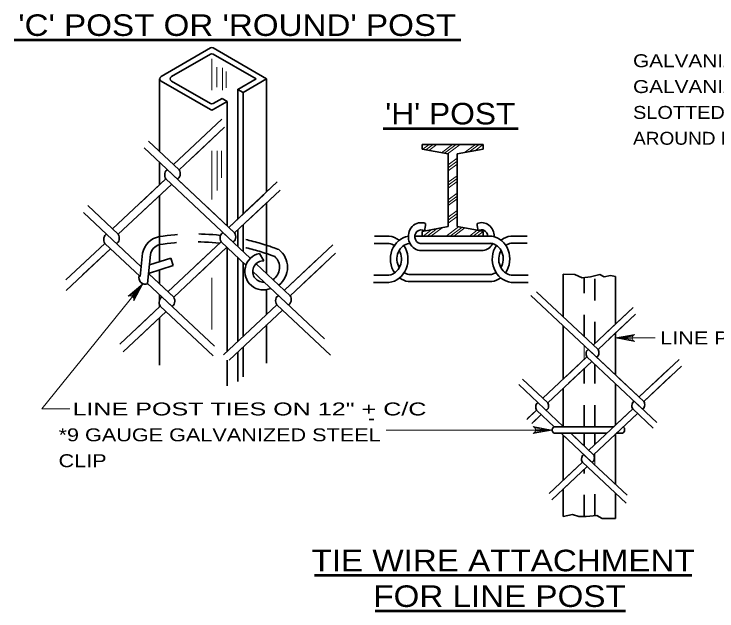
# Model space of a CAD drawing. Extents: x -29.89 to -22.78, y 99.65 to 109.34.
# Drawn here: x -29.886 to -26.626, y 106.552 to 109.322 of the extents above; entities that cross this region are included whole.
import ezdxf
from ezdxf.enums import TextEntityAlignment as Align

# ---------------------------------------------------------------- set-up
doc = ezdxf.new("R2010")
doc.units = 0
doc.header["$LTSCALE"] = 0.024
doc.linetypes.add('SHORT_DASHED', pattern=[2.7, 1.5, -1.2])
for name, color, linetype, lineweight in [('1', 7, 'Continuous', 35), ('10', 7, 'Continuous', 13), ('12', 7, 'Continuous', 53), ('6', 7, 'Continuous', 13)]:
    doc.layers.add(name, color=color, linetype=linetype, lineweight=lineweight)

msp = doc.modelspace()

# ---------------------------------------------------------------- linework, layer by layer
at = {"layer": '1'}
for p, q in [((-29.20419, 109.0319), (-28.9746, 109.16444)), ((-28.96237, 109.16444), (-28.71446, 109.02129)), ((-29.15529, 109.03187), (-28.9746, 109.13621)), ((-28.96237, 109.13621), (-28.76335, 109.02131)), ((-29.21104, 109.02129), (-29.21104, 108.68415)), ((-29.20419, 109.01071), (-28.9746, 108.87817)), ((-29.15529, 109.01071), (-28.9746, 108.9064)), ((-28.71446, 109.02129), (-28.82358, 108.95829)), ((-28.71446, 109.02129), (-28.71446, 108.84885)), ((-28.71446, 109.02129), (-28.71446, 108.49612)), ((-28.84802, 108.97242), (-28.82358, 108.95829)), ((-28.84802, 108.97242), (-28.84802, 108.37069)), ((-28.82358, 108.95829), (-28.82358, 108.83994)), ((-28.82358, 108.95829), (-28.82358, 108.39365)), ((-28.96237, 108.9064), (-28.92119, 108.93017)), ((-28.96237, 108.87817), (-28.89675, 108.91606)), ((-28.92119, 108.93017), (-28.89675, 108.91606)), ((-28.89675, 108.91606), (-28.89675, 108.82658)), ((-28.89675, 108.91606), (-28.89675, 108.33875)), ((-28.92231, 108.83435), (-29.14665, 108.62367)), ((-28.92231, 108.83435), (-29.07192, 108.69385)), ((-28.90896, 108.79671), (-29.11992, 108.59856)), ((-28.90894, 108.79671), (-29.05856, 108.65619)), ((-29.26156, 108.7316), (-29.11992, 108.59856)), ((-27.99302, 108.7171), (-27.71019, 108.7171)), ((-27.99302, 108.6949), (-27.99302, 108.7171)), ((-27.71019, 108.6949), (-27.71019, 108.7171)), ((-29.28173, 108.70033), (-28.86265, 108.30673)), ((-27.87181, 108.67267), (-27.99302, 108.6949)), ((-27.83142, 108.67267), (-27.71019, 108.6949)), ((-27.87181, 108.67267), (-27.87181, 108.33565)), ((-27.83142, 108.67267), (-27.83142, 108.33565)), ((-29.21104, 108.63394), (-29.21104, 108.52971)), ((-29.17338, 108.59856), (-28.86265, 108.30673)), ((-29.18227, 108.55673), (-29.42921, 108.32481)), ((-29.18227, 108.55673), (-29.29838, 108.44769)), ((-29.18227, 108.55673), (-28.87156, 108.2649)), ((-29.15554, 108.53162), (-29.40248, 108.29971)), ((-29.15554, 108.53162), (-29.28502, 108.41002)), ((-28.66506, 108.54252), (-28.88937, 108.33183)), ((-28.66506, 108.54252), (-28.81467, 108.402)), ((-28.65169, 108.50487), (-28.86265, 108.30673)), ((-28.65169, 108.50487), (-28.80129, 108.36435)), ((-29.21104, 108.4795), (-29.21104, 108.17287)), ((-28.88937, 108.33183), (-28.72779, 108.4836)), ((-29.54412, 108.43275), (-29.40248, 108.29971)), ((-29.00429, 108.43977), (-28.86265, 108.30673)), ((-28.86265, 108.30673), (-28.71444, 108.44594)), ((-28.71446, 108.44592), (-28.71446, 108.11733)), ((-29.56429, 108.40148), (-29.29558, 108.14912)), ((-28.82358, 108.34344), (-28.82358, 108.21981)), ((-27.87181, 108.33565), (-27.99302, 108.31344)), ((-27.83142, 108.33565), (-27.7366, 108.31827)), ((-28.9161, 108.30673), (-28.7901, 108.1884)), ((-28.84802, 108.32048), (-28.84802, 108.24277)), ((-28.1455, 108.29144), (-28.21429, 108.29144)), ((-27.8516, 108.29121), (-28.02675, 108.29121)), ((-27.99302, 108.29121), (-27.99302, 108.31344)), ((-27.99302, 108.29121), (-27.71019, 108.29121)), ((-27.8516, 108.29121), (-27.66979, 108.29121)), ((-27.73048, 108.31715), (-27.71019, 108.31344)), ((-27.71019, 108.29121), (-27.71019, 108.31344)), ((-27.5814, 108.29192), (-27.50613, 108.29192)), ((-28.92502, 108.2649), (-29.17194, 108.03298)), ((-28.92502, 108.2649), (-29.04112, 108.15583)), ((-28.92502, 108.2649), (-28.81021, 108.15706)), ((-27.5814, 108.25823), (-27.50529, 108.25823)), ((-29.46483, 108.25787), (-29.64521, 108.08848)), ((-29.4381, 108.23277), (-29.64379, 108.03958)), ((-29.46483, 108.25787), (-29.58094, 108.14881)), ((-29.4381, 108.23277), (-29.56758, 108.11117)), ((-29.46483, 108.25787), (-29.30021, 108.10323)), ((-28.89829, 108.23979), (-29.14521, 108.00787)), ((-28.89829, 108.23979), (-29.02775, 108.11819)), ((-28.89675, 108.23833), (-28.89675, 107.75798)), ((-28.40779, 108.25069), (-28.63212, 108.04)), ((-28.40779, 108.25069), (-28.5574, 108.11017)), ((-28.1455, 108.25775), (-28.21494, 108.25775)), ((-27.8516, 108.25787), (-28.00319, 108.25787)), ((-27.8516, 108.25787), (-27.67215, 108.25787)), ((-29.30021, 108.10323), (-29.28931, 108.21177)), ((-29.26687, 108.07194), (-29.25346, 108.2056)), ((-28.74788, 108.21135), (-28.72735, 108.17663)), ((-28.39444, 108.21302), (-28.6054, 108.0149)), ((-28.39444, 108.21302), (-28.54404, 108.07252)), ((-27.8516, 108.22454), (-28.0054, 108.22454)), ((-27.8516, 108.22454), (-27.71019, 108.22454)), ((-29.25827, 108.15762), (-29.15873, 108.18977)), ((-29.15873, 108.18977), (-29.14746, 108.15487)), ((-28.84802, 108.19256), (-28.84802, 107.80375)), ((-28.82358, 108.1696), (-28.82358, 107.82671)), ((-28.76335, 108.16325), (-28.6054, 108.0149)), ((-28.63212, 108.04), (-28.47054, 108.19177)), ((-29.26227, 108.11781), (-29.14746, 108.15487)), ((-29.21104, 108.13435), (-29.21104, 108.06971)), ((-28.6054, 108.0149), (-28.45717, 108.1541)), ((-29.26227, 108.11781), (-29.14521, 108.00787)), ((-29.25983, 108.11554), (-29.14521, 108.00787)), ((-29.25983, 108.11554), (-29.14521, 108.00787)), ((-28.77879, 108.12756), (-28.44525, 107.81427)), ((-28.14687, 108.10975), (-28.21775, 108.10975)), ((-27.8516, 108.11344), (-28.05521, 108.11344)), ((-27.8516, 108.11344), (-27.67162, 108.11344)), ((-27.58002, 108.11021), (-27.50163, 108.11021)), ((-27.33833, 107.9165), (-27.33833, 108.11508)), ((-27.09592, 107.88338), (-27.09592, 108.10408)), ((-29.26687, 108.07194), (-29.15413, 107.96604)), ((-28.14687, 108.07612), (-28.2184, 108.07612)), ((-27.8516, 108.0801), (-28.05765, 108.0801)), ((-27.8516, 108.0801), (-27.66927, 108.0801)), ((-27.58002, 108.0766), (-27.50079, 108.0766)), ((-28.71446, 108.04292), (-28.71446, 107.92919)), ((-27.462, 108.03265), (-27.1774, 107.76535)), ((-29.21104, 108.0195), (-29.21104, 107.99421)), ((-29.19867, 108.00787), (-28.95629, 107.78023)), ((-27.48862, 108.01615), (-26.96479, 107.52417)), ((-29.20758, 107.96604), (-29.39494, 107.79006)), ((-29.20758, 107.96604), (-29.32369, 107.85698)), ((-29.21104, 107.9735), (-29.21104, 107.96279)), ((-29.20758, 107.96604), (-28.96177, 107.73517)), ((-28.66775, 107.97304), (-28.91469, 107.74115)), ((-28.66775, 107.97304), (-28.41802, 107.7385)), ((-29.18085, 107.94092), (-29.37956, 107.75429)), ((-29.18085, 107.94092), (-29.31031, 107.81933)), ((-28.64102, 107.94794), (-28.88796, 107.71604)), ((-27.0141, 107.96023), (-27.1995, 107.7861)), ((-27.0141, 107.96023), (-27.13775, 107.84408)), ((-29.21104, 107.91256), (-29.21104, 107.69258)), ((-27.00306, 107.9291), (-27.1774, 107.76535)), ((-27.00304, 107.9291), (-27.12669, 107.81296)), ((-28.71446, 107.87898), (-28.71446, 107.70129)), ((-27.33833, 107.62802), (-27.33833, 107.875)), ((-27.09592, 107.64731), (-27.09592, 107.84188)), ((-28.82358, 107.7765), (-28.82358, 107.63829)), ((-28.84802, 107.75354), (-28.84802, 107.61735)), ((-27.22158, 107.76535), (-26.96479, 107.52417)), ((-28.89675, 107.71604), (-28.89675, 107.59606)), ((-27.22894, 107.73077), (-27.43302, 107.5391)), ((-27.20685, 107.71002), (-27.41092, 107.51835)), ((-27.22894, 107.73077), (-27.3249, 107.64065)), ((-27.20685, 107.71002), (-27.31385, 107.60952)), ((-27.22894, 107.73077), (-26.97215, 107.48958)), ((-26.80148, 107.71904), (-26.98687, 107.54492)), ((-26.80148, 107.71904), (-26.92512, 107.6029)), ((-26.79044, 107.68792), (-26.96479, 107.52417)), ((-26.79044, 107.68792), (-26.91408, 107.57177)), ((-26.98687, 107.54492), (-26.85333, 107.67033)), ((-26.96479, 107.52417), (-26.84229, 107.63921)), ((-27.52798, 107.62831), (-27.41092, 107.51835)), ((-27.08185, 107.6341), (-26.96479, 107.52417)), ((-27.54467, 107.60248), (-27.33833, 107.40869)), ((-27.33833, 107.40869), (-27.33833, 107.58654)), ((-27.09592, 107.41483), (-27.09592, 107.60581)), ((-27.00898, 107.52417), (-26.90483, 107.42635)), ((-27.46246, 107.48377), (-27.50819, 107.44083)), ((-27.46246, 107.48377), (-27.50379, 107.44496)), ((-27.46246, 107.48377), (-27.38052, 107.40681)), ((-27.01633, 107.48958), (-27.2204, 107.29792)), ((-27.01633, 107.48958), (-27.11229, 107.39946)), ((-27.01633, 107.48958), (-26.92146, 107.40046)), ((-27.44037, 107.46302), (-27.48454, 107.42156)), ((-27.44037, 107.46302), (-27.47352, 107.4319)), ((-26.99425, 107.46883), (-27.19831, 107.27717)), ((-26.99425, 107.46883), (-27.10125, 107.36833)), ((-27.38052, 107.40681), (-27.10446, 107.40681)), ((-27.38052, 107.37652), (-27.13671, 107.37652)), ((-27.34827, 107.37652), (-27.3264, 107.35598)), ((-27.34544, 107.37385), (-27.20567, 107.24258)), ((-27.33833, 107.1595), (-27.33833, 107.36719)), ((-27.30408, 107.37652), (-27.19831, 107.27717)), ((-27.29304, 107.36615), (-27.19831, 107.27717)), ((-27.29304, 107.36615), (-27.19831, 107.27717)), ((-27.09592, 107.1395), (-27.09592, 107.37335)), ((-27.09254, 107.37652), (-27.06448, 107.37652)), ((-27.2425, 107.27717), (-27.04219, 107.08904)), ((-27.24985, 107.24258), (-27.40471, 107.09717)), ((-27.22777, 107.22183), (-27.39198, 107.0676)), ((-27.24985, 107.24258), (-27.34581, 107.15248)), ((-27.22777, 107.22183), (-27.33477, 107.12135)), ((-27.24985, 107.24258), (-27.04671, 107.05179)), ((-27.33833, 106.98992), (-27.33833, 107.118)), ((-27.09592, 106.9804), (-27.09592, 107.098))]:
    msp.add_line(p, q, dxfattribs=at)
at = {"layer": '1', "linetype": 'SHORT_DASHED'}
for p, q in [((-27.24237, 107.82637), (-27.24237, 108.0994)), ((-27.19187, 107.79325), (-27.19187, 108.10725)), ((-27.24237, 107.40681), (-27.24237, 107.67667)), ((-27.19187, 107.40681), (-27.19187, 107.69594)), ((-27.24237, 107.31856), (-27.24237, 107.37652)), ((-27.19187, 107.32471), (-27.19187, 107.37652)), ((-27.24237, 106.99017), (-27.24237, 107.20812)), ((-27.19187, 106.99415), (-27.19187, 107.18812))]:
    msp.add_line(p, q, dxfattribs=at)
at = {"layer": '1', "linetype": 'SHORT_DASHED', "lineweight": 13}
for p, q in [((-27.24237, 107.71815), (-27.24237, 107.78487)), ((-27.19187, 107.22962), (-27.19187, 107.28323))]:
    msp.add_line(p, q, dxfattribs=at)
at = {"layer": '1'}
msp.add_lwpolyline([(-28.76335, 109.02131), (-28.84802, 108.97242), (-28.84802, 108.685)], dxfattribs=at)
for centre, radius, start, end in [((-28.96849, 109.15386), 0.01222, 60.0006, 119.99957), ((-28.96849, 109.12563), 0.01222, 59.99813, 120.00071), ((-29.19808, 109.0213), 0.01222, 119.99853, 240.00052), ((-29.14919, 109.0213), 0.01222, 119.99761, 240.00139), ((-28.96849, 108.91697), 0.01222, 240.00143, 299.99939), ((-28.96849, 108.88875), 0.01222, 239.99805, 300.00281), ((-29.19635, 108.19591), 0.09429, 98.95948, 170.31552), ((-29.19644, 108.19612), 0.0578, 104.6262, 170.56116), ((-29.04802, 107.21988), 1.08163, 68.83724, 72.03764), ((-28.72218, 108.14623), 0.10468, 308.12749, 51.85944), ((-28.72959, 108.12745), 0.08588, 102.29438, 293.75153), ((-29.04802, 107.21988), 1.04497, 69.16795, 71.38465), ((-28.72218, 108.14623), 0.06802, 303.38393, 47.6921), ((-28.72959, 108.12745), 0.04921, 87.39757, 273.71049), ((-29.27652, 108.0982), 0.03015, 161.37373, 292.21662), ((-27.37322, 107.39167), 0.01682, 115.75947, 244.31459), ((-27.07197, 107.393), 0.0181, 294.41167, 49.74746)]:
    msp.add_arc(centre, radius, start, end, dxfattribs=at)
at = {"layer": '1', "linetype": 'SHORT_DASHED'}
for radius, start, end in [(1.08163, 83.66437, 98.66828), (1.04497, 83.62275, 98.97491), (1.08163, 72.03764, 79.87877), (1.04497, 71.38466, 79.17127)]:
    msp.add_arc((-29.04802, 107.21988), radius, start, end, dxfattribs=at)
at = {"layer": '1'}
for centre, major_axis, ratio, start_param, end_param in [((-29.17246, 108.57462), (0, -0.02399), 0.614712, 3.2035127, 5.5543186), ((-29.12971, 108.58066), (0, 0.02398), 0.614712, 3.20226, 5.5556486), ((-27.99811, 108.28897), (0, -0.06492), 0.909091, 2.7881258, 6.1592385), ((-27.71749, 108.28897), (0, -0.06492), 0.909091, 1.567235, 3.4950595), ((-28.05979, 108.34574), (0, -0.09043), 0.909091, 1.2284532, 1.6165452), ((-27.6558, 108.34574), (0, -0.09043), 0.909091, 4.6666401, 5.0547321), ((-29.45502, 108.27576), (0, -0.02399), 0.614712, 3.2035127, 5.5543186), ((-29.45502, 108.27576), (0, -0.02399), 0.614712, 3.2035127, 5.5543186), ((-29.41227, 108.2818), (0, 0.02398), 0.614712, 3.20226, 5.5556486), ((-29.41227, 108.2818), (0, 0.02398), 0.614712, 3.20226, 5.5556486), ((-28.9152, 108.28278), (0, -0.02399), 0.614712, 3.2035127, 5.5543186), ((-28.87245, 108.28882), (0, 0.02398), 0.614712, 3.20226, 5.5556486), ((-28.04352, 108.18538), (0, 0.10642), 0.909091, 0.1409029, 2.222687), ((-28.15737, 108.18387), (0, 0.10835), 0.909091, 5.660064, 6.1623738), ((-27.99811, 108.28897), (0, -0.03159), 0.909091, 2.5612758, 6.4609907), ((-27.71749, 108.28897), (0, -0.03159), 0.909091, 1.6417945, 3.7219095), ((-27.68338, 108.18585), (0, 0.10642), 0.909091, 4.0604983, 6.1422825), ((-27.56953, 108.18434), (0, 0.10835), 0.909091, 0.1208115, 0.6231213), ((-27.68338, 108.18585), (0, 0.07308), 0.909091, 4.1290813, 6.1570752), ((-27.56953, 108.18434), (0, 0.07502), 0.909091, 0.1749584, 0.548513), ((-28.15737, 108.18387), (0, 0.10835), 0.909091, 3.2482898, 5.3446577), ((-28.15737, 108.18387), (0, 0.07502), 0.909091, 5.7346723, 6.1082269), ((-28.04352, 108.18538), (0, 0.07308), 0.909091, 0.1261101, 2.154104), ((-27.71749, 108.28897), (0, -0.06492), 0.909091, 0.1239468, 1.0358633), ((-27.56953, 108.18434), (0, 0.10835), 0.909091, 0.9385276, 3.0348955), ((-28.15737, 108.18387), (0, 0.07502), 0.909091, 3.296019, 5.2791696), ((-27.56953, 108.18434), (0, 0.07502), 0.909091, 1.0040157, 2.9871663), ((-28.04352, 108.18538), (0, 0.10642), 0.909091, 2.5436178, 2.9951503), ((-28.04352, 108.18538), (0, 0.07308), 0.909091, 2.6215535, 2.9648201), ((-27.68338, 108.18585), (0, 0.07308), 0.909091, 3.3183652, 3.6616318), ((-27.68338, 108.18585), (0, 0.10642), 0.909091, 3.288035, 3.7395675), ((-29.19776, 107.98393), (0, -0.02399), 0.614712, 3.2035127, 5.5543186), ((-29.19776, 107.98393), (0, -0.02399), 0.614712, 3.2035127, 5.5543186), ((-29.19776, 107.98393), (0, -0.02399), 0.614712, 3.2035127, 5.5543186), ((-29.15501, 107.98997), (0, 0.02398), 0.614712, 3.20226, 5.5556486), ((-29.15501, 107.98997), (0, 0.02398), 0.614712, 3.20226, 5.5556486), ((-29.15501, 107.98997), (0, 0.02398), 0.614712, 3.20226, 5.5556486), ((-28.65794, 107.99095), (0, -0.02399), 0.614712, 3.2035127, 5.5543186), ((-28.65794, 107.99095), (0, -0.02399), 0.614712, 3.2035127, 5.5543186), ((-28.61519, 107.99699), (0, 0.02398), 0.614712, 3.20226, 5.5556486), ((-27.22083, 107.74556), (0, -0.01983), 0.614712, 3.2035127, 5.5543186), ((-27.1855, 107.75055), (0, 0.01982), 0.614712, 3.20226, 5.5556486), ((-27.45435, 107.49857), (0, -0.01983), 0.614712, 3.2035127, 5.5543186), ((-27.45435, 107.49857), (0, -0.01983), 0.614712, 3.2035127, 5.5543186), ((-27.41902, 107.50356), (0, 0.01982), 0.614712, 3.20226, 5.5556486), ((-27.41902, 107.50356), (0, 0.01982), 0.614712, 3.20226, 5.5556486), ((-27.00822, 107.50437), (0, -0.01983), 0.614712, 3.2035127, 5.5543186), ((-26.97289, 107.50936), (0, 0.01982), 0.614712, 3.20226, 5.5556486), ((-27.24174, 107.25738), (0, -0.01983), 0.614712, 3.2035127, 5.5543186), ((-27.24174, 107.25738), (0, -0.01983), 0.614712, 3.2035127, 5.5543186), ((-27.24174, 107.25738), (0, -0.01983), 0.614712, 3.2035127, 5.5543186), ((-27.20641, 107.26237), (0, 0.01982), 0.614712, 3.20226, 5.5556486), ((-27.20641, 107.26237), (0, 0.01982), 0.614712, 3.20226, 5.5556486), ((-27.20641, 107.26237), (0, 0.01982), 0.614712, 3.20226, 5.5556486)]:
    msp.add_ellipse(centre, major_axis=major_axis, ratio=ratio, start_param=start_param, end_param=end_param, dxfattribs=at)
at = {"layer": '10'}
for p, q in [((-29.7564, 107.49044), (-29.28808, 108.07035)), ((-26.91187, 107.81908), (-27.09592, 107.81908)), ((-29.62762, 107.49044), (-29.7564, 107.49044)), ((-27.39004, 107.39167), (-28.16, 107.39167))]:
    msp.add_line(p, q, dxfattribs=at)
at = {"layer": '10', "lineweight": 35}
for points in [[(-27.33833, 108.11508), (-27.2855, 108.11292), (-27.25135, 108.09827), (-27.21231, 108.10315), (-27.18792, 108.10804), (-27.16842, 108.11292), (-27.1489, 108.10315), (-27.11962, 108.10804), (-27.09592, 108.10408)], [(-27.33833, 106.98992), (-27.29525, 106.99992), (-27.26598, 106.99017), (-27.23183, 106.99017), (-27.18304, 106.99504), (-27.15865, 106.9804), (-27.09592, 106.9804)]]:
    msp.add_lwpolyline(points, dxfattribs=at)
at = {"layer": '10'}
for points in [[(-29.28808, 108.07035), (-29.33067, 107.99129), (-29.33006, 107.99954), (-29.33246, 108.006), (-29.33644, 108.0105), (-29.34167, 108.01344), (-29.34848, 108.01442), (-29.35642, 108.01208), (-29.28808, 108.07035), (-29.34848, 108.01442), (-29.34167, 108.01344), (-29.28808, 108.07035), (-29.33644, 108.0105), (-29.33246, 108.006), (-29.28808, 108.07035), (-29.33006, 107.99954)], [(-27.09592, 107.81908), (-27.00765, 107.83562), (-27.01444, 107.83092), (-27.01796, 107.825), (-27.01896, 107.81908), (-27.01796, 107.81317), (-27.01444, 107.80723), (-27.00765, 107.80252), (-27.09592, 107.81908), (-27.01444, 107.80723), (-27.01796, 107.81317), (-27.09592, 107.81908), (-27.01896, 107.81908), (-27.01796, 107.825), (-27.09592, 107.81908), (-27.01444, 107.83092)], [(-27.39004, 107.39167), (-27.47831, 107.3751), (-27.4715, 107.37983), (-27.468, 107.38575), (-27.46698, 107.39167), (-27.468, 107.39758), (-27.4715, 107.4035), (-27.47831, 107.40821), (-27.39004, 107.39167), (-27.4715, 107.4035), (-27.468, 107.39758), (-27.39004, 107.39167), (-27.46698, 107.39167), (-27.468, 107.38575), (-27.39004, 107.39167), (-27.4715, 107.37983)]]:
    msp.add_lwpolyline(points, dxfattribs=at)
at = {"layer": '12'}
for p, q in [((-29.88569, 109.20177), (-27.81325, 109.20177)), ((-28.17354, 108.79102), (-27.54812, 108.79102)), ((-28.49233, 106.71756), (-26.74271, 106.71756)), ((-28.21056, 106.55204), (-27.04967, 106.55204))]:
    msp.add_line(p, q, dxfattribs=at)
at = {"layer": '6'}
for p, q in [((-28.96848, 109.11356), (-28.96848, 108.96852)), ((-28.94537, 109.07517), (-28.94537, 108.98294)), ((-28.9196, 109.07225), (-28.9196, 108.96852)), ((-28.90121, 109.05585), (-28.90121, 108.97965)), ((-27.95992, 108.7171), (-27.98998, 108.69433)), ((-27.9421, 108.7171), (-27.97565, 108.69171)), ((-27.92429, 108.7171), (-27.96131, 108.68906)), ((-27.85306, 108.7171), (-27.90396, 108.67856)), ((-27.83525, 108.7171), (-27.8896, 108.67594)), ((-27.81744, 108.7171), (-27.87527, 108.67329)), ((-27.74621, 108.7171), (-27.7964, 108.67908)), ((-27.7284, 108.7171), (-27.77292, 108.6834)), ((-27.71058, 108.7171), (-27.74942, 108.68771)), ((-28.96848, 108.68725), (-28.96848, 108.46088)), ((-28.94404, 108.68725), (-28.94404, 108.50279)), ((-28.9231, 108.68652), (-28.9231, 108.56221)), ((-27.83142, 108.65256), (-27.87181, 108.62196)), ((-27.83142, 108.63906), (-27.87181, 108.60846)), ((-27.83142, 108.62558), (-27.87181, 108.59498)), ((-27.83142, 108.57162), (-27.87181, 108.541)), ((-27.83142, 108.55812), (-27.87181, 108.52752)), ((-27.83142, 108.54462), (-27.87181, 108.51402)), ((-27.83142, 108.49067), (-27.87181, 108.46006)), ((-27.83142, 108.47719), (-27.87181, 108.44656)), ((-27.83142, 108.46369), (-27.87181, 108.43308)), ((-27.83142, 108.40973), (-27.87181, 108.3791)), ((-27.83142, 108.39623), (-27.87181, 108.36562)), ((-27.83142, 108.38275), (-27.87181, 108.35213)), ((-27.924, 108.32608), (-27.97004, 108.29121)), ((-27.9005, 108.3304), (-27.95223, 108.29121)), ((-27.8241, 108.33431), (-27.881, 108.29121)), ((-27.80975, 108.33169), (-27.86319, 108.29121)), ((-27.79542, 108.32906), (-27.84538, 108.29121)), ((-27.9475, 108.32177), (-27.98785, 108.29121)), ((-27.73806, 108.31854), (-27.77415, 108.29121)), ((-27.72373, 108.31592), (-27.75633, 108.29121)), ((-27.7094, 108.31329), (-27.73852, 108.29121)), ((-28.96848, 108.09827), (-28.96848, 107.85781))]:
    msp.add_line(p, q, dxfattribs=at)

# ---------------------------------------------------------------- texts
at = {"layer": '12'}
for s, height, width, p in [("'C' POST OR 'ROUND' POST", 0.1, 1.15, (-28.85055, 109.22036)), ("'H' POST", 0.1, 1.1, (-27.86258, 108.80962)), ('-', 0.06, 1.15, (-28.22781, 107.41744)), ('TIE WIRE ATTACHMENT', 0.1, 1.15, (-27.61752, 106.73616)), ('FOR LINE POST', 0.1, 1.15, (-27.63426, 106.57065))]:
    msp.add_text(s, height=height, dxfattribs=dict(at, width=width)).set_placement(p, align=Align.CENTER)
for s, width, p in [('GALVANIZED PRESSED STEEL OR', 1.2, (-27.01495, 109.0753)), ('GALVANIZED MALLEABLE IRON', 1.2, (-27.01495, 108.9553)), ('SLOTTED ATTACHMENT BOLTED', 1.15, (-27.01495, 108.8353)), ('AROUND POST.', 1.1, (-27.01495, 108.7153)), ('LINE POST', 1.25, (-26.88914, 107.78907)), ('  LINE POST TIES ON 12" + C/C ', 1.45, (-29.67938, 107.45922)), ('*9 GAUGE GALVANIZED STEEL', 1.25, (-29.67938, 107.33922)), ('CLIP', 1.25, (-29.67938, 107.21922))]:
    msp.add_text(s, height=0.06, dxfattribs=dict(at, width=width)).set_placement(p)

doc.saveas('drawing.dxf')
